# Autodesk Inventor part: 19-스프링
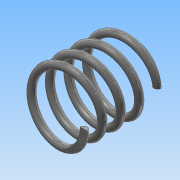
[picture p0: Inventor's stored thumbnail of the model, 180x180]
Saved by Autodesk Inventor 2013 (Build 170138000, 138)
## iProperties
Created: 2017-07
Part Number: 19-스프링
Material: 스테인리스강
Document SubType Name: Modeling
Designer: Administrator
Density: 8.08 g/cm^3
Mass: 5.30916 g
Surface Area: 13.3836 cm^2
Volume: 0.657075 cm^3
Author: Administrator
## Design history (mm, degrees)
sketch "스케치1"
  geometry: L1 (0, 0)-(0, 20.5); L2 (0, 0)-(8.5, 0); L3 (0, 20.5)-(8.5, 20.5); C1 r 1 at (8.5, 0)
  constraints: 6 end point, 1 centre point, 1 coincident, 1 parallel, 1 perpendicular, 1 vertical
  dimensions: "d0" = 20.5 distance of L1.start L1.end (derived); "d1" = 8.5 distance of L1.start L2.end; "d2" = 2 diameter of C1; "d3" = 8.5 distance of L1.end L3.end
feature "코일1" sketch "스케치1" pitch "d4" = 10; turns "d6" = 4; dims "d5" = 20.5 (= d0), "d7" = 0, angle "d8" = 90 deg, angle "d9" = 90 deg, "d10" = 0, "d11" = 0
sketch "스케치2"
  geometry: L1 (20.5, 15)-(0, 15); L2 (0, 15)-(0, -15); L3 (0, -15)-(20.5, -15); L4 (20.5, -15)-(20.5, 15); 2 further points
  constraints: 8 end point, 2 parallel, 1 coincident, 1 horizontal, 1 midpoint, 1 perpendicular
  dimensions: "d12" = 20.5 distance of L1.start L1.end (derived); "d14" = 30 distance of L3.end L1.start
extrude "돌출1" sketch "스케치2" stored distance "d15" = 10; taper "d16" = 0 deg
node "솔리드1"
